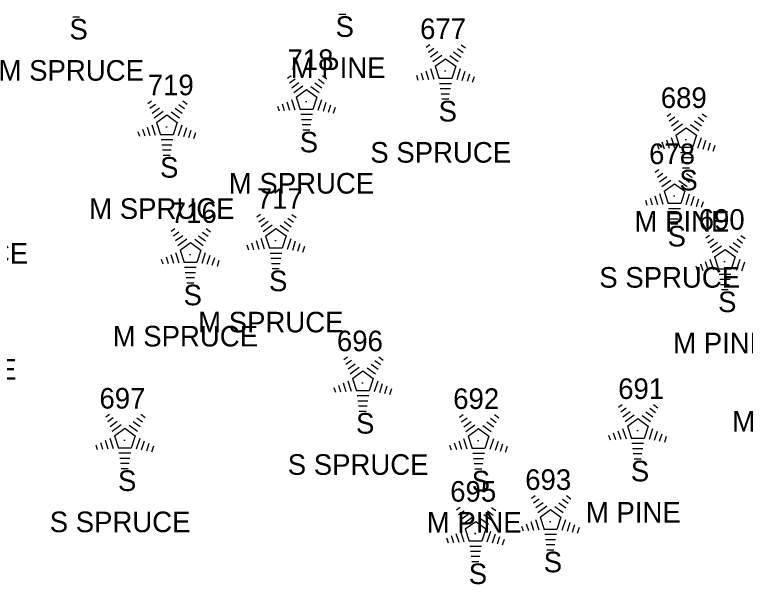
# Model space of a CAD drawing. Extents: x 1545627 to 1546562, y 571176 to 576667.
# Drawn here: x 1546217.9 to 1546288.8, y 572159.2 to 572214.5 of the extents above; entities that cross this region are included whole.
import ezdxf

# ---------------------------------------------------------------- set-up
doc = ezdxf.new("R2010")
doc.units = 0
for name, color, linetype in [('L_A', 7, 'Continuous'), ('L_C', 7, 'Continuous'), ('L_I', 7, 'Continuous'), ('LTC', 7, 'Continuous')]:
    doc.layers.add(name, color=color, linetype=linetype)

msp = doc.modelspace()

# ---------------------------------------------------------------- linework, layer by layer
at = {"layer": 'LTC'}
for p, q in [((1546224.166, 572214.286), (1546223.491, 572214.286)), ((1546250.008, 572214.541), (1546249.333, 572214.541)), ((1546257.827, 572211.375), (1546258.182, 572211.633)), ((1546258.037, 572210.91), (1546258.566, 572211.294)), ((1546260.854, 572211.267), (1546261.404, 572210.868)), ((1546261.226, 572211.615), (1546261.645, 572211.311)), ((1546258.246, 572210.444), (1546258.95, 572210.955)), ((1546258.456, 572209.978), (1546259.334, 572210.616)), ((1546260.112, 572210.57), (1546260.922, 572209.982)), ((1546260.483, 572210.919), (1546261.163, 572210.425)), ((1546258.681, 572209.523), (1546259.692, 572210.258)), ((1546259.692, 572210.258), (1546260.689, 572209.533)), ((1546257.771, 572209.088), (1546258.042, 572208.252)), ((1546258.226, 572209.304), (1546258.557, 572208.285)), ((1546258.681, 572209.523), (1546259.068, 572208.33)), ((1546260.689, 572209.533), (1546260.298, 572208.33)), ((1546261.127, 572209.262), (1546260.789, 572208.222)), ((1546244.339, 572208.374), (1546244.694, 572208.631)), ((1546247.738, 572208.614), (1546248.157, 572208.309)), ((1546256.86, 572208.654), (1546257.012, 572208.186)), ((1546257.315, 572208.871), (1546257.527, 572208.219)), ((1546261.571, 572209.011), (1546261.284, 572208.127)), ((1546262.016, 572208.761), (1546261.779, 572208.032)), ((1546262.46, 572208.511), (1546262.273, 572207.937)), ((1546244.549, 572207.908), (1546245.078, 572208.292)), ((1546244.758, 572207.442), (1546245.462, 572207.954)), ((1546246.995, 572207.917), (1546247.675, 572207.424)), ((1546247.366, 572208.266), (1546247.916, 572207.866)), ((1546260.298, 572208.33), (1546259.068, 572208.33)), ((1546260.26, 572207.83), (1546259.115, 572207.83)), ((1546244.968, 572206.976), (1546245.846, 572207.614)), ((1546245.193, 572206.521), (1546246.204, 572207.256)), ((1546246.204, 572207.256), (1546247.201, 572206.531)), ((1546246.624, 572207.569), (1546247.434, 572206.98)), ((1546260.176, 572207.33), (1546259.188, 572207.33)), ((1546244.738, 572206.302), (1546245.069, 572205.283)), ((1546245.193, 572206.521), (1546245.58, 572205.328)), ((1546247.201, 572206.531), (1546246.81, 572205.328)), ((1546247.639, 572206.26), (1546247.301, 572205.221)), ((1546260.092, 572206.83), (1546259.261, 572206.83)), ((1546260.008, 572206.33), (1546259.333, 572206.33)), ((1546230.782, 572205.918), (1546231.137, 572206.175)), ((1546230.992, 572205.453), (1546231.521, 572205.837)), ((1546233.809, 572205.81), (1546234.359, 572205.411)), ((1546234.181, 572206.158), (1546234.6, 572205.854)), ((1546243.372, 572205.653), (1546243.524, 572205.185)), ((1546243.827, 572205.869), (1546244.039, 572205.218)), ((1546244.283, 572206.086), (1546244.554, 572205.251)), ((1546248.083, 572206.01), (1546247.796, 572205.125)), ((1546248.528, 572205.76), (1546248.291, 572205.03)), ((1546248.972, 572205.509), (1546248.785, 572204.935)), ((1546231.202, 572204.987), (1546231.905, 572205.498)), ((1546231.411, 572204.521), (1546232.289, 572205.159)), ((1546231.636, 572204.066), (1546232.647, 572204.8)), ((1546232.647, 572204.8), (1546233.644, 572204.075)), ((1546233.067, 572205.113), (1546233.877, 572204.525)), ((1546233.439, 572205.462), (1546234.118, 572204.968)), ((1546246.81, 572205.328), (1546245.58, 572205.328)), ((1546246.772, 572204.828), (1546245.627, 572204.828)), ((1546281.207, 572204.682), (1546281.562, 572204.94)), ((1546284.605, 572204.923), (1546285.025, 572204.618)), ((1546246.688, 572204.328), (1546245.7, 572204.328)), ((1546281.417, 572204.217), (1546281.946, 572204.601)), ((1546281.626, 572203.751), (1546282.33, 572204.262)), ((1546283.863, 572204.226), (1546284.543, 572203.732)), ((1546284.234, 572204.574), (1546284.784, 572204.175)), ((1546230.27, 572203.414), (1546230.482, 572202.762)), ((1546230.726, 572203.63), (1546230.997, 572202.795)), ((1546231.181, 572203.847), (1546231.512, 572202.828)), ((1546231.636, 572204.066), (1546232.023, 572202.873)), ((1546233.644, 572204.075), (1546233.253, 572202.873)), ((1546234.082, 572203.805), (1546233.744, 572202.765)), ((1546234.526, 572203.554), (1546234.239, 572202.67)), ((1546246.604, 572203.828), (1546245.773, 572203.828)), ((1546281.836, 572203.285), (1546282.714, 572203.923)), ((1546282.06, 572202.83), (1546283.072, 572203.565)), ((1546283.072, 572203.565), (1546284.069, 572202.84)), ((1546283.492, 572203.878), (1546284.302, 572203.289)), ((1546229.815, 572203.197), (1546229.967, 572202.729)), ((1546233.253, 572202.873), (1546232.023, 572202.873)), ((1546234.971, 572203.304), (1546234.734, 572202.575)), ((1546235.415, 572203.054), (1546235.229, 572202.48)), ((1546246.52, 572203.328), (1546245.845, 572203.328)), ((1546282.06, 572202.83), (1546282.448, 572201.637)), ((1546284.069, 572202.84), (1546283.678, 572201.637)), ((1546233.215, 572202.373), (1546232.07, 572202.373)), ((1546280.24, 572201.961), (1546280.392, 572201.493)), ((1546280.695, 572202.178), (1546280.907, 572201.526)), ((1546281.15, 572202.395), (1546281.422, 572201.559)), ((1546281.606, 572202.611), (1546281.937, 572201.592)), ((1546284.507, 572202.569), (1546284.169, 572201.529)), ((1546284.951, 572202.318), (1546284.664, 572201.434)), ((1546285.396, 572202.068), (1546285.159, 572201.339)), ((1546233.131, 572201.873), (1546232.143, 572201.873)), ((1546233.047, 572201.373), (1546232.216, 572201.373)), ((1546283.678, 572201.637), (1546282.448, 572201.637)), ((1546285.84, 572201.818), (1546285.653, 572201.244)), ((1546232.964, 572200.873), (1546232.289, 572200.873)), ((1546283.64, 572201.137), (1546282.495, 572201.137)), ((1546283.556, 572200.637), (1546282.568, 572200.637)), ((1546283.472, 572200.137), (1546282.64, 572200.137)), ((1546280.063, 572199.238), (1546280.417, 572199.496)), ((1546280.272, 572198.773), (1546280.802, 572199.157)), ((1546283.388, 572199.637), (1546282.713, 572199.637)), ((1546283.09, 572199.13), (1546283.64, 572198.731)), ((1546283.461, 572199.479), (1546283.88, 572199.174)), ((1546280.482, 572198.307), (1546281.186, 572198.818)), ((1546280.692, 572197.841), (1546281.57, 572198.479)), ((1546282.348, 572198.434), (1546283.157, 572197.845)), ((1546282.719, 572198.782), (1546283.398, 572198.288)), ((1546280.916, 572197.386), (1546281.928, 572198.121)), ((1546281.928, 572198.121), (1546282.925, 572197.396)), ((1546280.462, 572197.167), (1546280.792, 572196.148)), ((1546280.916, 572197.386), (1546281.303, 572196.193)), ((1546282.925, 572197.396), (1546282.534, 572196.193)), ((1546283.362, 572197.125), (1546283.025, 572196.085)), ((1546279.095, 572196.517), (1546279.247, 572196.049)), ((1546279.551, 572196.734), (1546279.762, 572196.082)), ((1546280.006, 572196.951), (1546280.277, 572196.115)), ((1546283.807, 572196.874), (1546283.52, 572195.99)), ((1546284.252, 572196.624), (1546284.015, 572195.895)), ((1546284.696, 572196.374), (1546284.509, 572195.8)), ((1546282.534, 572196.193), (1546281.303, 572196.193)), ((1546282.495, 572195.693), (1546281.351, 572195.693)), ((1546241.362, 572194.895), (1546241.717, 572195.153)), ((1546244.761, 572195.136), (1546245.18, 572194.831)), ((1546282.412, 572195.193), (1546281.423, 572195.193)), ((1546241.572, 572194.43), (1546242.101, 572194.814)), ((1546241.782, 572193.964), (1546242.485, 572194.475)), ((1546244.019, 572194.439), (1546244.698, 572193.945)), ((1546244.39, 572194.787), (1546244.939, 572194.388)), ((1546282.328, 572194.693), (1546281.496, 572194.693)), ((1546282.244, 572194.193), (1546281.569, 572194.193)), ((1546233.064, 572193.529), (1546233.418, 572193.787)), ((1546233.273, 572193.064), (1546233.802, 572193.448)), ((1546236.462, 572193.77), (1546236.881, 572193.465)), ((1546241.991, 572193.498), (1546242.87, 572194.136)), ((1546242.216, 572193.043), (1546243.227, 572193.778)), ((1546243.227, 572193.778), (1546244.225, 572193.053)), ((1546243.647, 572194.091), (1546244.457, 572193.502)), ((1546233.483, 572192.598), (1546234.187, 572193.109)), ((1546233.692, 572192.132), (1546234.571, 572192.77)), ((1546235.72, 572193.073), (1546236.399, 572192.579)), ((1546236.091, 572193.421), (1546236.64, 572193.022)), ((1546241.761, 572192.824), (1546242.092, 572191.805)), ((1546242.216, 572193.043), (1546242.603, 572191.85)), ((1546244.225, 572193.053), (1546243.833, 572191.85)), ((1546244.662, 572192.782), (1546244.324, 572191.742)), ((1546284.968, 572192.865), (1546285.323, 572193.123)), ((1546285.178, 572192.4), (1546285.707, 572192.784)), ((1546287.995, 572192.757), (1546288.545, 572192.358)), ((1546288.366, 572193.106), (1546288.786, 572192.801)), ((1546233.917, 572191.677), (1546234.929, 572192.412)), ((1546234.929, 572192.412), (1546235.926, 572191.687)), ((1546235.349, 572192.725), (1546236.158, 572192.136)), ((1546240.395, 572192.174), (1546240.547, 572191.707)), ((1546240.85, 572192.391), (1546241.062, 572191.739)), ((1546241.306, 572192.608), (1546241.577, 572191.772)), ((1546245.107, 572192.532), (1546244.819, 572191.647)), ((1546245.551, 572192.282), (1546245.314, 572191.552)), ((1546245.995, 572192.031), (1546245.809, 572191.457)), ((1546285.387, 572191.934), (1546286.091, 572192.445)), ((1546285.597, 572191.468), (1546286.475, 572192.106)), ((1546287.253, 572192.061), (1546288.063, 572191.472)), ((1546287.624, 572192.409), (1546288.303, 572191.915)), ((1546233.462, 572191.458), (1546233.793, 572190.439)), ((1546233.917, 572191.677), (1546234.304, 572190.484)), ((1546235.926, 572191.687), (1546235.534, 572190.484)), ((1546236.363, 572191.416), (1546236.025, 572190.376)), ((1546243.833, 572191.85), (1546242.603, 572191.85)), ((1546243.795, 572191.35), (1546242.65, 572191.35)), ((1546285.821, 572191.013), (1546286.833, 572191.748)), ((1546286.833, 572191.748), (1546287.83, 572191.023)), ((1546232.096, 572190.808), (1546232.248, 572190.34)), ((1546232.552, 572191.025), (1546232.763, 572190.373)), ((1546233.007, 572191.242), (1546233.278, 572190.406)), ((1546236.808, 572191.165), (1546236.52, 572190.281)), ((1546237.252, 572190.915), (1546237.015, 572190.186)), ((1546237.697, 572190.665), (1546237.51, 572190.091)), ((1546243.711, 572190.85), (1546242.723, 572190.85)), ((1546285.367, 572190.794), (1546285.698, 572189.775)), ((1546285.821, 572191.013), (1546286.208, 572189.82)), ((1546287.83, 572191.023), (1546287.439, 572189.82)), ((1546288.268, 572190.752), (1546287.93, 572189.712)), ((1546235.534, 572190.484), (1546234.304, 572190.484)), ((1546235.496, 572189.984), (1546234.352, 572189.984)), ((1546243.627, 572190.35), (1546242.796, 572190.35)), ((1546284.001, 572190.144), (1546284.153, 572189.677)), ((1546284.456, 572190.361), (1546284.668, 572189.709)), ((1546284.911, 572190.578), (1546285.183, 572189.742)), ((1546288.712, 572190.502), (1546288.425, 572189.617)), ((1546235.412, 572189.484), (1546234.424, 572189.484)), ((1546243.544, 572189.85), (1546242.869, 572189.85)), ((1546287.439, 572189.82), (1546286.208, 572189.82)), ((1546287.401, 572189.32), (1546286.256, 572189.32)), ((1546235.329, 572188.984), (1546234.497, 572188.984)), ((1546235.245, 572188.484), (1546234.57, 572188.484)), ((1546287.317, 572188.82), (1546286.328, 572188.82)), ((1546287.233, 572188.32), (1546286.401, 572188.32)), ((1546287.149, 572187.82), (1546286.474, 572187.82)), ((1546249.809, 572181.067), (1546250.164, 572181.325)), ((1546250.019, 572180.602), (1546250.548, 572180.986)), ((1546252.836, 572180.959), (1546253.386, 572180.56)), ((1546253.207, 572181.308), (1546253.627, 572181.003)), ((1546250.228, 572180.136), (1546250.932, 572180.647)), ((1546250.438, 572179.67), (1546251.316, 572180.308)), ((1546252.094, 572180.263), (1546252.904, 572179.674)), ((1546252.465, 572180.611), (1546253.144, 572180.117)), ((1546250.662, 572179.215), (1546251.674, 572179.95)), ((1546251.674, 572179.95), (1546252.671, 572179.225)), ((1546249.297, 572178.563), (1546249.509, 572177.911)), ((1546249.752, 572178.78), (1546250.024, 572177.944)), ((1546250.208, 572178.996), (1546250.539, 572177.977)), ((1546250.662, 572179.215), (1546251.049, 572178.022)), ((1546252.671, 572179.225), (1546252.28, 572178.022)), ((1546253.109, 572178.954), (1546252.771, 572177.914)), ((1546253.553, 572178.704), (1546253.266, 572177.819)), ((1546248.842, 572178.346), (1546248.994, 572177.879)), ((1546252.28, 572178.022), (1546251.049, 572178.022)), ((1546253.998, 572178.454), (1546253.761, 572177.724)), ((1546254.442, 572178.203), (1546254.255, 572177.629)), ((1546252.242, 572177.522), (1546251.097, 572177.522)), ((1546252.158, 572177.022), (1546251.169, 572177.022)), ((1546252.074, 572176.522), (1546251.242, 572176.522)), ((1546276.494, 572176.432), (1546276.849, 572176.69)), ((1546279.893, 572176.673), (1546280.312, 572176.368)), ((1546226.696, 572175.5), (1546227.05, 572175.757)), ((1546230.094, 572175.74), (1546230.513, 572175.436)), ((1546251.99, 572176.022), (1546251.315, 572176.022)), ((1546261.044, 572175.461), (1546261.399, 572175.719)), ((1546276.704, 572175.967), (1546277.233, 572176.351)), ((1546276.913, 572175.501), (1546277.617, 572176.012)), ((1546279.15, 572175.976), (1546279.83, 572175.482)), ((1546279.521, 572176.324), (1546280.071, 572175.925)), ((1546226.905, 572175.034), (1546227.435, 572175.418)), ((1546227.115, 572174.568), (1546227.819, 572175.08)), ((1546229.352, 572175.043), (1546230.031, 572174.55)), ((1546229.723, 572175.392), (1546230.273, 572174.993)), ((1546261.254, 572174.996), (1546261.783, 572175.38)), ((1546261.463, 572174.53), (1546262.167, 572175.041)), ((1546263.7, 572175.005), (1546264.379, 572174.511)), ((1546264.071, 572175.353), (1546264.621, 572174.954)), ((1546264.442, 572175.701), (1546264.861, 572175.397)), ((1546277.123, 572175.035), (1546278.001, 572175.673)), ((1546277.348, 572174.58), (1546278.359, 572175.315)), ((1546278.359, 572175.315), (1546279.356, 572174.59)), ((1546278.779, 572175.628), (1546279.589, 572175.039)), ((1546227.325, 572174.103), (1546228.203, 572174.741)), ((1546227.549, 572173.648), (1546228.561, 572174.382)), ((1546228.561, 572174.382), (1546229.558, 572173.657)), ((1546228.981, 572174.695), (1546229.79, 572174.106)), ((1546261.673, 572174.064), (1546262.551, 572174.702)), ((1546261.897, 572173.609), (1546262.909, 572174.344)), ((1546262.909, 572174.344), (1546263.906, 572173.619)), ((1546263.329, 572174.656), (1546264.139, 572174.068)), ((1546276.893, 572174.361), (1546277.224, 572173.342)), ((1546277.348, 572174.58), (1546277.735, 572173.387)), ((1546279.356, 572174.59), (1546278.965, 572173.387)), ((1546279.794, 572174.319), (1546279.456, 572173.279)), ((1546227.549, 572173.648), (1546227.936, 572172.454)), ((1546229.558, 572173.657), (1546229.167, 572172.454)), ((1546261.897, 572173.609), (1546262.284, 572172.416)), ((1546263.906, 572173.619), (1546263.515, 572172.416)), ((1546275.527, 572173.711), (1546275.679, 572173.244)), ((1546275.982, 572173.928), (1546276.194, 572173.276)), ((1546276.438, 572174.145), (1546276.709, 572173.309)), ((1546280.238, 572174.069), (1546279.951, 572173.184)), ((1546280.683, 572173.819), (1546280.446, 572173.089)), ((1546226.184, 572172.996), (1546226.395, 572172.344)), ((1546226.639, 572173.212), (1546226.91, 572172.377)), ((1546227.095, 572173.428), (1546227.425, 572172.409)), ((1546229.995, 572173.386), (1546229.658, 572172.347)), ((1546230.44, 572173.136), (1546230.153, 572172.251)), ((1546230.885, 572172.886), (1546230.648, 572172.156)), ((1546260.532, 572172.957), (1546260.744, 572172.305)), ((1546260.987, 572173.174), (1546261.259, 572172.338)), ((1546261.443, 572173.39), (1546261.774, 572172.371)), ((1546264.344, 572173.348), (1546264.006, 572172.308)), ((1546264.788, 572173.097), (1546264.501, 572172.213)), ((1546278.965, 572173.387), (1546277.735, 572173.387)), ((1546278.927, 572172.887), (1546277.782, 572172.887)), ((1546281.127, 572173.568), (1546280.94, 572172.994)), ((1546225.728, 572172.779), (1546225.88, 572172.311)), ((1546229.167, 572172.454), (1546227.936, 572172.454)), ((1546231.329, 572172.636), (1546231.142, 572172.061)), ((1546260.076, 572172.74), (1546260.229, 572172.272)), ((1546263.515, 572172.416), (1546262.284, 572172.416)), ((1546265.233, 572172.847), (1546264.996, 572172.118)), ((1546265.677, 572172.597), (1546265.49, 572172.023)), ((1546278.843, 572172.387), (1546277.855, 572172.387)), ((1546229.128, 572171.954), (1546227.984, 572171.954)), ((1546229.045, 572171.454), (1546228.056, 572171.454)), ((1546263.476, 572171.916), (1546262.332, 572171.916)), ((1546278.759, 572171.887), (1546277.928, 572171.887)), ((1546228.961, 572170.954), (1546228.129, 572170.954)), ((1546263.393, 572171.416), (1546262.404, 572171.416)), ((1546263.309, 572170.916), (1546262.477, 572170.916)), ((1546278.675, 572171.387), (1546278, 572171.387)), ((1546228.877, 572170.454), (1546228.202, 572170.454)), ((1546263.225, 572170.416), (1546262.55, 572170.416)), ((1546268.035, 572167.603), (1546268.39, 572167.861)), ((1546268.245, 572167.138), (1546268.774, 572167.522)), ((1546271.062, 572167.495), (1546271.612, 572167.096)), ((1546271.433, 572167.844), (1546271.853, 572167.539)), ((1546260.755, 572166.46), (1546261.11, 572166.718)), ((1546264.153, 572166.7), (1546264.572, 572166.396)), ((1546268.454, 572166.672), (1546269.158, 572167.183)), ((1546268.664, 572166.206), (1546269.542, 572166.844)), ((1546268.888, 572165.751), (1546269.9, 572166.486)), ((1546269.9, 572166.486), (1546270.897, 572165.761)), ((1546270.32, 572166.799), (1546271.13, 572166.21)), ((1546270.691, 572167.147), (1546271.371, 572166.653)), ((1546260.965, 572165.995), (1546261.494, 572166.379)), ((1546261.174, 572165.529), (1546261.878, 572166.04)), ((1546263.411, 572166.004), (1546264.09, 572165.51)), ((1546263.782, 572166.352), (1546264.332, 572165.953)), ((1546261.384, 572165.063), (1546262.262, 572165.701)), ((1546261.608, 572164.608), (1546262.62, 572165.343)), ((1546262.62, 572165.343), (1546263.617, 572164.618)), ((1546263.04, 572165.655), (1546263.85, 572165.067)), ((1546267.523, 572165.099), (1546267.735, 572164.448)), ((1546267.978, 572165.316), (1546268.25, 572164.48)), ((1546268.434, 572165.532), (1546268.765, 572164.513)), ((1546268.888, 572165.751), (1546269.276, 572164.558)), ((1546270.897, 572165.761), (1546270.506, 572164.558)), ((1546271.335, 572165.49), (1546270.997, 572164.45)), ((1546271.779, 572165.24), (1546271.492, 572164.355)), ((1546261.154, 572164.389), (1546261.485, 572163.37)), ((1546261.608, 572164.608), (1546261.995, 572163.415)), ((1546263.617, 572164.618), (1546263.226, 572163.415)), ((1546267.068, 572164.883), (1546267.22, 572164.415)), ((1546270.506, 572164.558), (1546269.276, 572164.558)), ((1546272.224, 572164.99), (1546271.987, 572164.26)), ((1546272.668, 572164.739), (1546272.481, 572164.165)), ((1546259.787, 572163.739), (1546259.94, 572163.271)), ((1546260.243, 572163.956), (1546260.455, 572163.304)), ((1546260.698, 572164.173), (1546260.97, 572163.337)), ((1546264.055, 572164.347), (1546263.717, 572163.307)), ((1546264.499, 572164.096), (1546264.212, 572163.212)), ((1546264.944, 572163.846), (1546264.707, 572163.117)), ((1546270.468, 572164.058), (1546269.323, 572164.058)), ((1546263.226, 572163.415), (1546261.995, 572163.415)), ((1546265.388, 572163.596), (1546265.201, 572163.022)), ((1546270.384, 572163.558), (1546269.396, 572163.558)), ((1546270.3, 572163.058), (1546269.468, 572163.058)), ((1546263.187, 572162.915), (1546262.043, 572162.915)), ((1546263.104, 572162.415), (1546262.115, 572162.415)), ((1546270.216, 572162.558), (1546269.541, 572162.558)), ((1546263.02, 572161.915), (1546262.188, 572161.915)), ((1546262.936, 572161.415), (1546262.261, 572161.415))]:
    msp.add_line(p, q, dxfattribs=at)

# ---------------------------------------------------------------- texts
at = {"layer": 'L_A'}
for p in [(1546223.175, 572212.124), (1546249.017, 572212.378), (1546259.018, 572204.167), (1546245.53, 572201.165), (1546231.973, 572198.71), (1546282.398, 572197.474), (1546281.254, 572192.03), (1546242.553, 572187.687), (1546234.254, 572186.321), (1546286.159, 572185.657), (1546251, 572173.859), (1546277.685, 572169.224), (1546227.887, 572168.292), (1546262.235, 572168.253), (1546269.226, 572160.395), (1546261.946, 572159.252)]:
    msp.add_text('S', height=2, dxfattribs=at).set_placement(p)
at = {"layer": 'L_C'}
for s, p in [('M SPRUCE', (1546216.293, 572208.124)), ('M PINE', (1546244.655, 572208.378)), ('S SPRUCE', (1546252.388, 572200.167)), ('M SPRUCE', (1546238.648, 572197.165)), ('M SPRUCE', (1546225.091, 572194.71)), ('M PINE', (1546278.036, 572193.474)), ('M SPRUCE', (1546205.048, 572190.357)), ('S SPRUCE', (1546274.624, 572188.03)), ('M SPRUCE', (1546235.671, 572183.687)), ('M SPRUCE', (1546227.372, 572182.321)), ('M PINE', (1546281.796, 572181.657)), ('M PINE', (1546208.832, 572179.102)), ('M SPRUCE', (1546287.531, 572174.061)), ('S SPRUCE', (1546244.37, 572169.859)), ('M PINE', (1546273.323, 572165.224)), ('S SPRUCE', (1546221.257, 572164.292)), ('M PINE', (1546257.872, 572164.253))]:
    msp.add_text(s, height=2, dxfattribs=at).set_placement(p)
at = {"layer": 'L_I'}
for s, p in [('677', (1546257.223, 572212.167)), ('718', (1546244.349, 572209.165)), ('719', (1546230.784, 572206.71)), ('689', (1546280.595, 572205.474)), ('678', (1546279.458, 572200.03)), ('717', (1546241.372, 572195.687)), ('716', (1546233.018, 572194.321)), ('690', (1546284.277, 572193.657)), ('696', (1546249.149, 572181.859)), ('691', (1546276.457, 572177.224)), ('697', (1546226.091, 572176.292)), ('692', (1546260.439, 572176.253)), ('693', (1546267.431, 572168.395)), ('695', (1546260.15, 572167.252))]:
    msp.add_text(s, height=2, dxfattribs=at).set_placement(p)
at = {"layer": 'LTC'}
for p in [(1546259.575, 572209.271), (1546246.087, 572206.269), (1546232.53, 572203.814), (1546282.955, 572202.578), (1546281.81, 572197.134), (1546243.11, 572192.791), (1546234.811, 572191.425), (1546286.716, 572190.761), (1546251.557, 572178.963), (1546278.242, 572174.328), (1546228.443, 572173.396), (1546262.791, 572173.357), (1546269.783, 572165.499), (1546262.502, 572164.356)]:
    msp.add_text('.', height=1.037, rotation=270, dxfattribs=at).set_placement(p)

doc.saveas('drawing.dxf')
